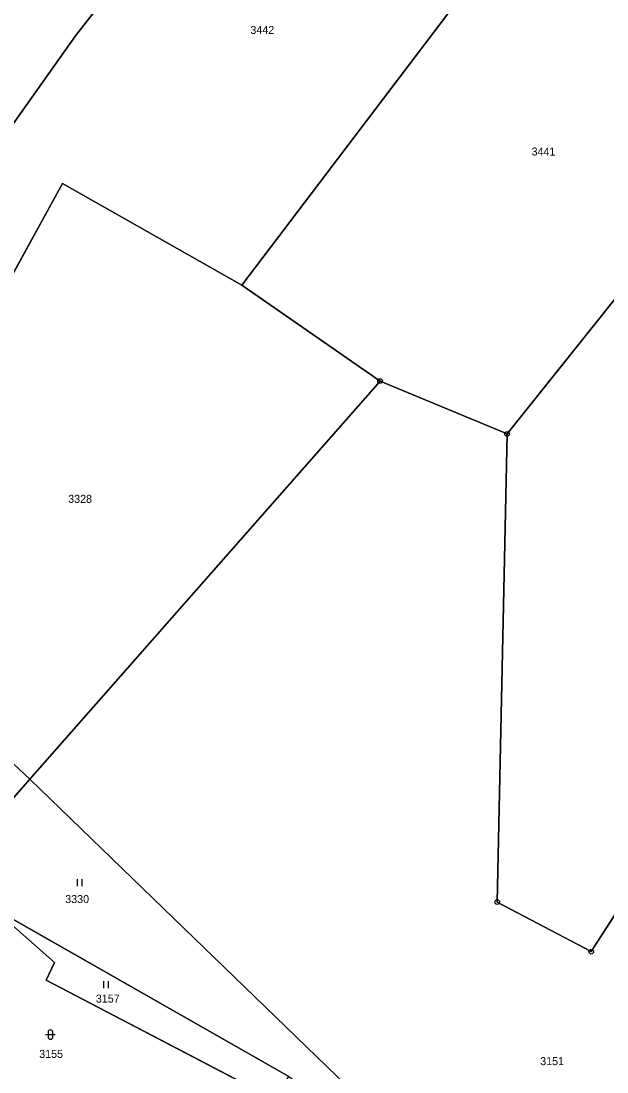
# Model space of a CAD drawing. Extents: x -689422 to -685210, y -987725 to -982160.
# Drawn here: x -688140 to -688015.4, y -984533.7 to -984310.4 of the extents above; entities that cross this region are included whole.
import ezdxf

# ---------------------------------------------------------------- set-up
doc = ezdxf.new("R2010")
doc.units = 0
for name, color, linetype in [('KN_Hranice_parcel', 7, 'Continuous'), ('KN_Parcelni cisla', 7, 'Continuous'), ('KN_Polygon parcely', 7, 'Continuous'), ('KN_POZEMKY_ORNA PUDA', 7, 'Continuous'), ('KN_POZEMKY_OSTATNI PLOCHA', 7, 'Continuous'), ('KN_POZEMKY_TTP', 7, 'Continuous'), ('KN_VYUZITI_27_ostatni plocha_neplodna puda', 7, 'Continuous'), ('KN_Značky bodu BP', 7, 'Continuous'), ('KN_Značky kultur', 7, 'Continuous')]:
    doc.layers.add(name, color=color, linetype=linetype)

msp = doc.modelspace()

# ---------------------------------------------------------------- linework, layer by layer
at = {"layer": 'KN_Hranice_parcel'}
for p, q in [((-688012.19, -984259.97), (-688093.07, -984366.55)), ((-688036.67, -984398.13), (-687967.89, -984312.04)), ((-688063.67, -984386.89), (-688093.07, -984366.55)), ((-688138.1, -984471.52), (-688063.67, -984386.89)), ((-688063.67, -984386.89), (-688036.67, -984398.13)), ((-688155.6, -984491.42), (-688138.1, -984471.52)), ((-688083.05, -984534.66), (-688146.21, -984498.69))]:
    msp.add_line(p, q, dxfattribs=at)
for points in [[(-688061.91, -984228.49), (-688128.41, -984313.54), (-688144.94, -984336.87), (-688156.47, -984329.82), (-688185.08, -984374.83), (-688202.14, -984406.52)], [(-688093.07, -984366.55), (-688131.12, -984344.89), (-688178.73, -984431.48)], [(-687981.52, -984489.7), (-688000.34, -984479.38), (-688018.78, -984508.15), (-688038.77, -984497.61), (-688036.67, -984398.13)], [(-688178.73, -984431.48), (-688155.93, -984454.88), (-688138.1, -984471.52)], [(-688138.1, -984471.52), (-688070.62, -984536.75), (-688063.54, -984548.47)], [(-688086.31, -984539.4), (-688134.62, -984514.23), (-688132.86, -984510.47), (-688146.21, -984498.69)]]:
    msp.add_lwpolyline(points, dxfattribs=at)
at = {"layer": 'KN_Polygon parcely'}
for points in [[(-688180.26, -984295.06), (-688229.17, -984377.69), (-688202.14, -984406.52), (-688185.08, -984374.83), (-688156.47, -984329.82), (-688144.94, -984336.87), (-688128.41, -984313.54), (-688061.91, -984228.49), (-688096.34, -984204.36), (-688173.88, -984302.32)], [(-688015.18, -984257.18), (-688032.88, -984243.92), (-688046.42, -984234.47), (-688053.93, -984234.17), (-688061.91, -984228.49), (-688128.41, -984313.54), (-688144.94, -984336.87), (-688156.47, -984329.82), (-688185.08, -984374.83), (-688202.14, -984406.52), (-688178.73, -984431.48), (-688131.12, -984344.89), (-688093.07, -984366.55), (-688012.19, -984259.97)], [(-688012.19, -984259.97), (-688093.07, -984366.55), (-688063.67, -984386.89), (-688036.67, -984398.13), (-687967.89, -984312.04), (-687983.99, -984289.86), (-688001.37, -984269.78), (-688010, -984262.02)], [(-687967.89, -984312.04), (-688036.67, -984398.13), (-688038.77, -984497.61), (-688018.78, -984508.15), (-688000.34, -984479.38), (-687981.52, -984489.7), (-687996.2, -984455.49), (-688003.9, -984431.71), (-687884.94, -984444.64), (-687895.33, -984417.54), (-687904.81, -984399.91), (-687915.47, -984385.16)], [(-688093.07, -984366.55), (-688131.12, -984344.89), (-688178.73, -984431.48), (-688155.93, -984454.88), (-688138.1, -984471.52), (-688063.67, -984386.89)], [(-688018.78, -984508.15), (-688038.77, -984497.61), (-688036.67, -984398.13), (-688063.67, -984386.89), (-688138.1, -984471.52), (-688070.62, -984536.75), (-688063.54, -984548.47), (-688053.86, -984555.32), (-688045.6, -984559.12), (-688018.61, -984573.88), (-688016.2, -984568.61), (-688009.94, -984560.13), (-687920.07, -984592.32), (-687873.24, -984602.1), (-687877.19, -984534.71), (-687980.81, -984496.41), (-687981.52, -984489.7), (-688000.34, -984479.38)], [(-688155.6, -984491.42), (-688138.1, -984471.52), (-688155.93, -984454.88), (-688178.73, -984431.48), (-688205.49, -984479.62), (-688162.99, -984488.16)], [(-688146.21, -984498.69), (-688083.05, -984534.66), (-688063.54, -984548.47), (-688070.62, -984536.75), (-688138.1, -984471.52), (-688155.6, -984491.42)], [(-688160.42, -984524.79), (-688152.99, -984529.93), (-688148.04, -984545.3), (-688140.16, -984544.44), (-688129.51, -984543.28), (-688100.36, -984550.96), (-688096.14, -984553.67), (-688086.31, -984539.4), (-688134.62, -984514.23), (-688132.86, -984510.47), (-688146.21, -984498.69), (-688156.72, -984492.7), (-688164.71, -984499.51), (-688168.43, -984497.47), (-688175.9, -984501.25), (-688170.46, -984507.28), (-688162.39, -984518.27)], [(-688146.21, -984498.69), (-688132.86, -984510.47), (-688134.62, -984514.23), (-688086.31, -984539.4), (-688083.05, -984534.66)]]:
    msp.add_lwpolyline(points, close=True, dxfattribs=at)
at = {"layer": 'KN_POZEMKY_ORNA PUDA'}
for p, q in [((-688128.41, -984313.54), (-688061.91, -984228.49)), ((-688061.91, -984228.49), (-688128.41, -984313.54)), ((-688093.07, -984366.55), (-688012.19, -984259.97)), ((-688012.19, -984259.97), (-688093.07, -984366.55)), ((-688144.94, -984336.87), (-688128.41, -984313.54)), ((-688128.41, -984313.54), (-688144.94, -984336.87)), ((-687967.89, -984312.04), (-688036.67, -984398.13)), ((-688036.67, -984398.13), (-687967.89, -984312.04)), ((-688131.12, -984344.89), (-688178.73, -984431.48)), ((-688178.73, -984431.48), (-688131.12, -984344.89)), ((-688093.07, -984366.55), (-688131.12, -984344.89)), ((-688131.12, -984344.89), (-688093.07, -984366.55)), ((-688063.67, -984386.89), (-688093.07, -984366.55)), ((-688093.07, -984366.55), (-688063.67, -984386.89)), ((-688063.67, -984386.89), (-688138.1, -984471.52)), ((-688138.1, -984471.52), (-688063.67, -984386.89)), ((-688036.67, -984398.13), (-688063.67, -984386.89)), ((-688063.67, -984386.89), (-688036.67, -984398.13)), ((-688038.77, -984497.61), (-688036.67, -984398.13)), ((-688036.67, -984398.13), (-688038.77, -984497.61)), ((-688138.1, -984471.52), (-688155.93, -984454.88)), ((-688070.62, -984536.75), (-688138.1, -984471.52)), ((-688000.34, -984479.38), (-688018.78, -984508.15)), ((-688018.78, -984508.15), (-688000.34, -984479.38)), ((-688018.78, -984508.15), (-688038.77, -984497.61)), ((-688038.77, -984497.61), (-688018.78, -984508.15))]:
    msp.add_line(p, q, dxfattribs=at)
at = {"layer": 'KN_POZEMKY_OSTATNI PLOCHA'}
for p, q in [((-688146.21, -984498.69), (-688132.86, -984510.47)), ((-688132.86, -984510.47), (-688134.62, -984514.23)), ((-688134.62, -984514.23), (-688086.31, -984539.4))]:
    msp.add_line(p, q, dxfattribs=at)
at = {"layer": 'KN_POZEMKY_TTP'}
for p, q in [((-688155.93, -984454.88), (-688138.1, -984471.52)), ((-688155.6, -984491.42), (-688138.1, -984471.52)), ((-688138.1, -984471.52), (-688155.6, -984491.42)), ((-688138.1, -984471.52), (-688070.62, -984536.75)), ((-688083.05, -984534.66), (-688146.21, -984498.69)), ((-688132.86, -984510.47), (-688146.21, -984498.69)), ((-688146.21, -984498.69), (-688083.05, -984534.66)), ((-688134.62, -984514.23), (-688132.86, -984510.47)), ((-688086.31, -984539.4), (-688134.62, -984514.23))]:
    msp.add_line(p, q, dxfattribs=at)
at = {"layer": 'KN_VYUZITI_27_ostatni plocha_neplodna puda'}
for p, q in [((-688146.21, -984498.69), (-688132.86, -984510.47)), ((-688132.86, -984510.47), (-688134.62, -984514.23)), ((-688134.62, -984514.23), (-688086.31, -984539.4))]:
    msp.add_line(p, q, dxfattribs=at)
at = {"layer": 'KN_Značky bodu BP'}
for centre, radius in [((-688063.67, -984386.89), 0.5), ((-688063.67, -984386.89), 0.0303), ((-688036.67, -984398.13), 0.5), ((-688036.67, -984398.13), 0.0303), ((-688038.77, -984497.61), 0.5), ((-688038.77, -984497.61), 0.0303), ((-688018.78, -984508.15), 0.5), ((-688018.78, -984508.15), 0.0303)]:
    msp.add_circle(centre, radius, dxfattribs=at)
at = {"layer": 'KN_Značky kultur'}
for p, q in [((-688127.97, -984494.22), (-688127.97, -984492.72)), ((-688126.97, -984494.22), (-688126.97, -984492.72)), ((-688122.38, -984515.92), (-688122.38, -984514.42)), ((-688121.38, -984515.92), (-688121.38, -984514.42)), ((-688134.73, -984525.77), (-688132.73, -984525.77)), ((-688134.23, -984525.27), (-688134.23, -984526.27)), ((-688133.23, -984526.27), (-688133.23, -984525.27))]:
    msp.add_line(p, q, dxfattribs=at)
for centre, start, end in [((-688133.73, -984525.27), 0, 180), ((-688133.73, -984526.27), 180, 359.9879)]:
    msp.add_arc(centre, 0.5, start, end, dxfattribs=at)

# ---------------------------------------------------------------- texts
at = {"layer": 'KN_Parcelni cisla'}
for s, p in [('3442', (-688091.22, -984313.14)), ('3441', (-688031.46, -984338.97)), ('3328', (-688129.94, -984412.78)), ('3330', (-688130.57, -984497.82)), ('3157', (-688124.06, -984518.97)), ('3155', (-688136.1, -984530.73)), ('3151', (-688029.63, -984532.26))]:
    msp.add_text(s, height=1.7, dxfattribs=at).set_placement(p)

doc.saveas('drawing.dxf')
